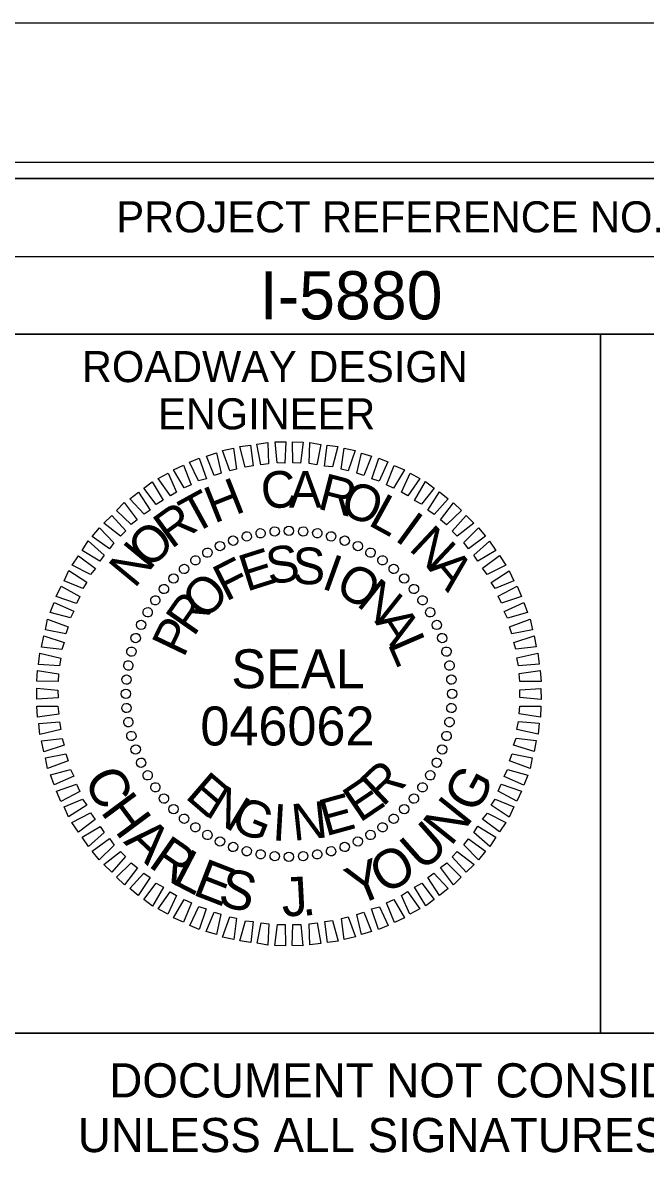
# Model space of a CAD drawing. Extents: x 1648157 to 1650776, y 832691 to 834781.
# Drawn here: x 1650336.4 to 1650436.6, y 833605.5 to 833791 of the extents above; entities that cross this region are included whole.
import ezdxf

# ---------------------------------------------------------------- set-up
doc = ezdxf.new("R2010")
doc.units = 0
for name, color, linetype in [('Default', 7, 'Continuous'), ('Old_Level_2', 7, 'Continuous'), ('Sheet Cutting Line CELL', 7, 'Continuous'), ('Sheet Data Field CELL', 7, 'Continuous'), ('Sheet Plot Border Inside CELL', 7, 'Continuous'), ('Sheet Plot Border Outside CELL', 7, 'Continuous'), ('Sheet Profile CELL', 7, 'Continuous'), ('Sheet Profile Grid Major CELL', 7, 'Continuous'), ('Sheet Sticker Exception Certification CELL', 7, 'Continuous')]:
    doc.layers.add(name, color=color, linetype=linetype)

msp = doc.modelspace()

# ---------------------------------------------------------------- linework, layer by layer
at = {"layer": 'Old_Level_2'}
for p, q in [((1650374.65, 833708.89), (1650374.65, 833708.89)), ((1650376.9, 833709.25), (1650376.9, 833709.25)), ((1650379.2, 833709.34), (1650379.2, 833709.34)), ((1650381.5, 833709.22), (1650381.5, 833709.22)), ((1650383.75, 833708.9), (1650383.75, 833708.9)), ((1650368.1, 833706.9), (1650368.1, 833706.9)), ((1650370.18, 833707.77), (1650370.18, 833707.77)), ((1650372.36, 833708.44), (1650372.36, 833708.44)), ((1650385.96, 833708.46), (1650385.96, 833708.46)), ((1650388.17, 833707.77), (1650388.17, 833707.77)), ((1650390.27, 833706.87), (1650390.27, 833706.87)), ((1650366.08, 833705.82), (1650366.08, 833705.82)), ((1650392.33, 833705.86), (1650392.33, 833705.86)), ((1650362.31, 833703.24), (1650362.31, 833703.24)), ((1650364.11, 833704.58), (1650364.11, 833704.58)), ((1650394.24, 833704.58), (1650394.24, 833704.58)), ((1650396.09, 833703.2), (1650396.09, 833703.2)), ((1650360.61, 833701.64), (1650360.61, 833701.64)), ((1650397.74, 833701.66), (1650397.74, 833701.66)), ((1650359.07, 833699.99), (1650359.07, 833699.99)), ((1650399.34, 833699.96), (1650399.34, 833699.96)), ((1650357.69, 833698.14), (1650357.69, 833698.14)), ((1650400.68, 833698.16), (1650400.68, 833698.16)), ((1650356.42, 833696.23), (1650356.42, 833696.23)), ((1650401.91, 833696.19), (1650401.91, 833696.19)), ((1650355.41, 833694.18), (1650355.41, 833694.18)), ((1650402.99, 833694.17), (1650402.99, 833694.17)), ((1650354.5, 833692.07), (1650354.5, 833692.07)), ((1650403.87, 833692.09), (1650403.87, 833692.09)), ((1650353.81, 833689.86), (1650353.81, 833689.86)), ((1650404.53, 833689.91), (1650404.53, 833689.91)), ((1650353.37, 833687.66), (1650353.37, 833687.66)), ((1650404.99, 833687.62), (1650404.99, 833687.62)), ((1650353.05, 833685.4), (1650353.05, 833685.4)), ((1650405.34, 833685.37), (1650405.34, 833685.37)), ((1650352.93, 833683.1), (1650352.93, 833683.1)), ((1650379.18, 833683.09), (1650379.18, 833683.09)), ((1650405.44, 833683.07), (1650405.44, 833683.07)), ((1650353.02, 833680.8), (1650353.02, 833680.8)), ((1650405.32, 833680.77), (1650405.32, 833680.77)), ((1650353.38, 833678.56), (1650353.38, 833678.56)), ((1650404.99, 833678.52), (1650404.99, 833678.52)), ((1650353.84, 833676.26), (1650353.84, 833676.26)), ((1650404.56, 833676.31), (1650404.56, 833676.31)), ((1650354.5, 833674.08), (1650354.5, 833674.08)), ((1650403.87, 833674.1), (1650403.87, 833674.1)), ((1650355.37, 833672), (1650355.37, 833672)), ((1650402.96, 833672), (1650402.96, 833672)), ((1650356.46, 833669.98), (1650356.46, 833669.98)), ((1650401.95, 833669.94), (1650401.95, 833669.94)), ((1650357.69, 833668.02), (1650357.69, 833668.02)), ((1650400.68, 833668.03), (1650400.68, 833668.03)), ((1650359.03, 833666.21), (1650359.03, 833666.21)), ((1650399.3, 833666.18), (1650399.3, 833666.18)), ((1650360.63, 833664.51), (1650360.63, 833664.51)), ((1650397.76, 833664.53), (1650397.76, 833664.53)), ((1650362.28, 833662.97), (1650362.28, 833662.97)), ((1650396.06, 833662.93), (1650396.06, 833662.93)), ((1650364.13, 833661.59), (1650364.13, 833661.59)), ((1650366.04, 833660.32), (1650366.04, 833660.32)), ((1650392.29, 833660.36), (1650392.29, 833660.36)), ((1650394.25, 833661.59), (1650394.25, 833661.59)), ((1650368.09, 833659.31), (1650368.09, 833659.31)), ((1650390.27, 833659.28), (1650390.27, 833659.28)), ((1650370.2, 833658.4), (1650370.2, 833658.4)), ((1650372.41, 833657.71), (1650372.41, 833657.71)), ((1650374.61, 833657.28), (1650374.61, 833657.28)), ((1650376.87, 833656.95), (1650376.87, 833656.95)), ((1650379.17, 833656.83), (1650379.17, 833656.83)), ((1650381.47, 833656.93), (1650381.47, 833656.93)), ((1650383.71, 833657.28), (1650383.71, 833657.28)), ((1650386.01, 833657.74), (1650386.01, 833657.74)), ((1650388.19, 833658.4), (1650388.19, 833658.4))]:
    msp.add_line(p, q, dxfattribs=at)
for points in [[(1650374.67, 833719.93), (1650374.04, 833723.26), (1650375.81, 833723.5), (1650375.92, 833720.11)], [(1650377.28, 833720.24), (1650376.96, 833723.63), (1650378.69, 833723.61), (1650378.54, 833720.21)], [(1650379.79, 833720.23), (1650379.73, 833723.63), (1650381.46, 833723.6), (1650381.05, 833720.2)], [(1650382.41, 833720.12), (1650382.56, 833723.52), (1650384.29, 833723.23), (1650383.67, 833719.93)], [(1650367.17, 833718.23), (1650365.91, 833721.34), (1650367.53, 833721.84), (1650368.26, 833718.61)], [(1650369.67, 833718.95), (1650368.51, 833722.23), (1650370.28, 833722.62), (1650370.76, 833719.23)], [(1650372.17, 833719.57), (1650371.27, 833722.9), (1650373, 833723.09), (1650373.42, 833719.75)], [(1650384.92, 833719.74), (1650385.34, 833723.1), (1650387.07, 833722.86), (1650386.18, 833719.61)], [(1650387.6, 833719.21), (1650388.06, 833722.62), (1650389.85, 833722.23), (1650388.7, 833718.97)], [(1650390.12, 833718.58), (1650390.85, 833721.83), (1650392.48, 833721.34), (1650391.23, 833718.23)], [(1650362.34, 833716.21), (1650360.62, 833719.11), (1650362.23, 833719.87), (1650363.48, 833716.7)], [(1650364.62, 833717.35), (1650363.21, 833720.36), (1650364.77, 833721.01), (1650365.92, 833717.68)], [(1650392.49, 833717.68), (1650393.64, 833720.99), (1650395.11, 833720.39), (1650393.7, 833717.33)], [(1650394.86, 833716.72), (1650396.11, 833719.83), (1650397.75, 833719.13), (1650396.02, 833716.17)], [(1650360.12, 833714.92), (1650358.13, 833717.71), (1650359.74, 833718.57), (1650361.1, 833715.56)], [(1650397.29, 833715.56), (1650398.65, 833718.57), (1650400.23, 833717.71), (1650398.29, 833714.95)], [(1650357.84, 833713.57), (1650355.86, 833716.2), (1650357.2, 833717.22), (1650358.98, 833714.22)], [(1650399.35, 833714.19), (1650401.13, 833717.25), (1650402.51, 833716.18), (1650400.51, 833713.58)], [(1650355.88, 833711.97), (1650353.59, 833714.44), (1650354.98, 833715.56), (1650356.86, 833712.66)], [(1650401.52, 833712.66), (1650403.41, 833715.57), (1650404.79, 833714.44), (1650402.53, 833711.94)], [(1650353.82, 833710.31), (1650351.48, 833712.57), (1650352.71, 833713.85), (1650354.8, 833711.06)], [(1650403.54, 833711.07), (1650405.63, 833713.83), (1650406.91, 833712.59), (1650404.54, 833710.3)], [(1650352.12, 833708.45), (1650349.42, 833710.55), (1650350.71, 833711.77), (1650352.94, 833709.3)], [(1650405.45, 833709.27), (1650407.66, 833711.77), (1650408.93, 833710.54), (1650406.25, 833708.45)], [(1650350.33, 833706.43), (1650347.57, 833708.42), (1650348.7, 833709.8), (1650351.04, 833707.38)], [(1650407.31, 833707.42), (1650409.68, 833709.82), (1650410.8, 833708.43), (1650408.06, 833706.39)], [(1650348.79, 833704.42), (1650345.94, 833706.14), (1650346.91, 833707.68), (1650349.46, 833705.42)], [(1650408.92, 833705.41), (1650411.44, 833707.65), (1650412.46, 833706.15), (1650409.56, 833704.43)], [(1650347.26, 833702.3), (1650344.31, 833703.81), (1650345.33, 833705.3), (1650348.08, 833703.25)], [(1650410.31, 833703.29), (1650413.05, 833705.33), (1650414.07, 833703.78), (1650411.06, 833702.26)], [(1650346.05, 833700.03), (1650343.04, 833701.28), (1650343.8, 833702.92), (1650346.66, 833701.03)], [(1650411.71, 833701.02), (1650414.61, 833702.9), (1650415.32, 833701.29), (1650412.36, 833700.03)], [(1650345.04, 833697.6), (1650341.78, 833698.75), (1650342.54, 833700.38), (1650345.55, 833698.76)], [(1650412.8, 833698.79), (1650415.86, 833700.41), (1650416.56, 833698.75), (1650413.34, 833697.65)], [(1650344.04, 833695.29), (1650340.78, 833696.17), (1650341.43, 833697.8), (1650344.59, 833696.39)], [(1650413.78, 833696.35), (1650416.95, 833697.76), (1650417.55, 833696.15), (1650414.32, 833695.26)], [(1650343.3, 833692.76), (1650340.04, 833693.39), (1650340.38, 833695.12), (1650343.7, 833693.87)], [(1650414.66, 833693.85), (1650417.99, 833695.11), (1650418.33, 833693.39), (1650415.05, 833692.76)], [(1650342.66, 833690.24), (1650339.41, 833690.6), (1650339.75, 833692.39), (1650343.06, 833691.35)], [(1650415.33, 833691.35), (1650418.61, 833692.4), (1650418.95, 833690.63), (1650415.67, 833690.26)], [(1650342.29, 833687.57), (1650338.94, 833687.82), (1650339.12, 833689.6), (1650342.53, 833688.83)], [(1650415.85, 833688.85), (1650419.23, 833689.64), (1650419.42, 833687.87), (1650416.08, 833687.6)], [(1650342.07, 833685.05), (1650338.67, 833685.1), (1650338.75, 833686.83), (1650342.15, 833686.31)], [(1650416.21, 833686.35), (1650419.6, 833686.82), (1650419.73, 833685.05), (1650416.33, 833685.09)], [(1650342.07, 833682.44), (1650338.67, 833682.22), (1650338.64, 833684), (1650342.04, 833683.69)], [(1650416.3, 833683.73), (1650419.7, 833683.95), (1650419.73, 833682.17), (1650416.33, 833682.48)], [(1650342.16, 833679.83), (1650338.77, 833679.35), (1650338.64, 833681.12), (1650342.04, 833681.08)], [(1650416.3, 833681.12), (1650419.7, 833681.07), (1650419.62, 833679.35), (1650416.21, 833679.86)], [(1650342.52, 833677.32), (1650339.14, 833676.53), (1650338.95, 833678.3), (1650342.29, 833678.57)], [(1650416.08, 833678.61), (1650419.43, 833678.35), (1650419.25, 833676.57), (1650415.84, 833677.35)], [(1650343.04, 833674.82), (1650339.76, 833673.77), (1650339.41, 833675.54), (1650342.7, 833675.91)], [(1650415.71, 833675.93), (1650418.96, 833675.57), (1650418.62, 833673.79), (1650415.31, 833674.83)], [(1650343.71, 833672.32), (1650340.38, 833671.06), (1650340.04, 833672.78), (1650343.32, 833673.41)], [(1650415.07, 833673.41), (1650418.32, 833672.79), (1650417.99, 833671.06), (1650414.67, 833672.31)], [(1650344.59, 833669.83), (1650341.42, 833668.41), (1650340.82, 833670.02), (1650344.04, 833670.92)], [(1650414.33, 833670.89), (1650417.59, 833670), (1650416.94, 833668.37), (1650413.78, 833669.78)], [(1650345.57, 833667.39), (1650342.51, 833665.76), (1650341.8, 833667.42), (1650345.03, 833668.53)], [(1650413.33, 833668.57), (1650416.59, 833667.42), (1650415.83, 833665.79), (1650412.82, 833667.41)], [(1650346.66, 833665.16), (1650343.76, 833663.28), (1650343.05, 833664.88), (1650346.01, 833666.14)], [(1650412.32, 833666.15), (1650415.33, 833664.89), (1650414.57, 833663.26), (1650411.71, 833665.14)], [(1650348.05, 833662.88), (1650345.32, 833660.84), (1650344.3, 833662.4), (1650347.3, 833663.91)], [(1650411.11, 833663.88), (1650414.06, 833662.36), (1650413.04, 833660.88), (1650410.29, 833662.92)], [(1650349.45, 833660.76), (1650346.93, 833658.52), (1650345.91, 833660.02), (1650348.81, 833661.74)], [(1650409.57, 833661.76), (1650412.43, 833660.03), (1650411.46, 833658.5), (1650408.91, 833660.75)], [(1650351.06, 833658.75), (1650348.69, 833656.35), (1650347.57, 833657.75), (1650350.31, 833659.78)], [(1650408.04, 833659.74), (1650410.8, 833657.75), (1650409.67, 833656.37), (1650407.33, 833658.79)], [(1650352.92, 833656.9), (1650350.71, 833654.4), (1650349.44, 833655.63), (1650352.12, 833657.72)], [(1650406.25, 833657.72), (1650408.95, 833655.63), (1650407.66, 833654.4), (1650405.42, 833656.87)], [(1650354.83, 833655.1), (1650352.74, 833652.35), (1650351.46, 833653.58), (1650353.83, 833655.87)], [(1650404.55, 833655.86), (1650406.89, 833653.6), (1650405.66, 833652.33), (1650403.57, 833655.12)], [(1650356.85, 833653.52), (1650354.96, 833650.61), (1650353.58, 833651.73), (1650355.84, 833654.23)], [(1650402.49, 833654.21), (1650404.78, 833651.74), (1650403.39, 833650.61), (1650401.51, 833653.51)], [(1650359.02, 833651.98), (1650357.24, 833648.92), (1650355.86, 833649.99), (1650357.86, 833652.59)], [(1650361.08, 833650.61), (1650359.72, 833647.6), (1650358.14, 833648.46), (1650360.08, 833651.22)], [(1650398.25, 833651.26), (1650400.24, 833648.47), (1650398.63, 833647.6), (1650397.27, 833650.61)], [(1650400.53, 833652.6), (1650402.51, 833649.97), (1650401.17, 833648.95), (1650399.39, 833651.96)], [(1650363.51, 833649.45), (1650362.25, 833646.34), (1650360.62, 833647.04), (1650362.35, 833650)], [(1650396.03, 833649.96), (1650397.75, 833647.06), (1650396.14, 833646.3), (1650394.88, 833649.47)], [(1650365.88, 833648.5), (1650364.73, 833645.18), (1650363.26, 833645.78), (1650364.67, 833648.84)], [(1650368.25, 833647.6), (1650367.52, 833644.34), (1650365.89, 833644.83), (1650367.14, 833647.94)], [(1650391.2, 833647.94), (1650392.46, 833644.83), (1650390.84, 833644.33), (1650390.11, 833647.56)], [(1650393.75, 833648.82), (1650395.16, 833645.82), (1650393.6, 833645.16), (1650392.44, 833648.49)], [(1650370.77, 833646.96), (1650370.3, 833643.55), (1650368.52, 833643.94), (1650369.67, 833647.2)], [(1650373.44, 833646.43), (1650373.03, 833643.08), (1650371.3, 833643.31), (1650372.19, 833646.57)], [(1650375.96, 833646.06), (1650375.81, 833642.65), (1650374.08, 833642.94), (1650374.7, 833646.24)], [(1650378.58, 833645.95), (1650378.64, 833642.55), (1650376.91, 833642.57), (1650377.32, 833645.98)], [(1650381.09, 833645.94), (1650381.41, 833642.54), (1650379.68, 833642.57), (1650379.83, 833645.97)], [(1650383.7, 833646.24), (1650384.33, 833642.91), (1650382.56, 833642.67), (1650382.45, 833646.07)], [(1650386.2, 833646.6), (1650387.1, 833643.27), (1650385.37, 833643.08), (1650384.95, 833646.42)], [(1650388.7, 833647.22), (1650389.86, 833643.95), (1650388.09, 833643.55), (1650387.61, 833646.94)]]:
    msp.add_lwpolyline(points, close=True, dxfattribs=at)
for centre, major_axis in [((1650370.21, 833707.73), (-0.258, 0.708)), ((1650372.4, 833708.42), (-0.195, 0.727)), ((1650374.63, 833708.92), (-0.131, 0.742)), ((1650376.9, 833709.21), (-0.066, 0.75)), ((1650379.18, 833709.31), (0, 0.753)), ((1650381.47, 833709.21), (0.066, 0.75)), ((1650383.74, 833708.92), (0.131, 0.742)), ((1650385.97, 833708.42), (0.195, 0.727)), ((1650388.15, 833707.73), (0.258, 0.708)), ((1650368.1, 833706.86), (-0.318, 0.682)), ((1650390.27, 833706.86), (0.318, 0.682)), ((1650364.14, 833704.57), (-0.432, 0.617)), ((1650366.07, 833705.8), (-0.376, 0.652)), ((1650392.3, 833705.8), (0.376, 0.652)), ((1650394.23, 833704.57), (0.432, 0.617)), ((1650362.33, 833703.18), (-0.484, 0.577)), ((1650396.04, 833703.18), (0.484, 0.577)), ((1650360.64, 833701.63), (-0.532, 0.532)), ((1650397.73, 833701.63), (0.532, 0.532)), ((1650359.09, 833699.95), (-0.577, 0.484)), ((1650399.28, 833699.95), (0.577, 0.484)), ((1650357.7, 833698.13), (-0.617, 0.432)), ((1650400.67, 833698.13), (0.617, 0.432)), ((1650356.47, 833696.2), (-0.652, 0.376)), ((1650401.9, 833696.2), (0.652, 0.376)), ((1650355.41, 833694.17), (-0.682, 0.318)), ((1650402.95, 833694.17), (0.682, 0.318)), ((1650354.54, 833692.06), (-0.708, 0.258)), ((1650403.83, 833692.06), (0.708, 0.258)), ((1650353.85, 833689.87), (-0.727, 0.195)), ((1650404.52, 833689.87), (0.727, 0.195)), ((1650353.36, 833687.64), (-0.742, 0.131)), ((1650405.01, 833687.64), (0.742, 0.131)), ((1650353.06, 833685.37), (-0.75, 0.066)), ((1650405.31, 833685.37), (0.75, 0.066)), ((1650352.96, 833683.09), (-0.753, 0)), ((1650405.41, 833683.09), (0.753, 0)), ((1650353.06, 833680.8), (-0.75, -0.066)), ((1650405.31, 833680.8), (0.75, -0.066)), ((1650353.36, 833678.53), (-0.742, -0.131)), ((1650405.01, 833678.53), (0.742, -0.131)), ((1650353.85, 833676.3), (-0.727, -0.195)), ((1650404.52, 833676.3), (0.727, -0.195)), ((1650354.54, 833674.12), (-0.708, -0.258)), ((1650403.83, 833674.12), (0.708, -0.258)), ((1650355.41, 833672), (-0.682, -0.318)), ((1650402.95, 833672), (0.682, -0.318)), ((1650356.47, 833669.97), (-0.652, -0.376)), ((1650401.9, 833669.97), (0.652, -0.376)), ((1650357.7, 833668.04), (-0.617, -0.432)), ((1650400.67, 833668.04), (0.617, -0.432)), ((1650359.09, 833666.23), (-0.577, -0.484)), ((1650399.28, 833666.23), (0.577, -0.484)), ((1650360.64, 833664.54), (-0.532, -0.532)), ((1650397.73, 833664.54), (0.532, -0.532)), ((1650362.33, 833662.99), (-0.484, -0.577)), ((1650364.14, 833661.6), (-0.432, -0.617)), ((1650394.23, 833661.6), (0.432, -0.617)), ((1650396.04, 833662.99), (0.484, -0.577)), ((1650366.07, 833660.37), (-0.376, -0.652)), ((1650392.3, 833660.37), (0.376, -0.652)), ((1650368.1, 833659.32), (-0.318, -0.682)), ((1650370.21, 833658.44), (-0.258, -0.708)), ((1650372.4, 833657.75), (-0.195, -0.727)), ((1650385.97, 833657.75), (0.195, -0.727)), ((1650388.15, 833658.44), (0.258, -0.708)), ((1650390.27, 833659.32), (0.318, -0.682)), ((1650374.63, 833657.26), (-0.131, -0.742)), ((1650376.9, 833656.96), (-0.066, -0.75)), ((1650379.18, 833656.86), (0, -0.753)), ((1650381.47, 833656.96), (0.066, -0.75)), ((1650383.74, 833657.26), (0.131, -0.742))]:
    msp.add_ellipse(centre, major_axis=major_axis, ratio=0.999708, dxfattribs=at)
at = {"layer": 'Sheet Cutting Line CELL'}
msp.add_line((1650546.28, 833791.02), (1648862.28, 833791.02), dxfattribs=at)
at = {"layer": 'Sheet Plot Border Inside CELL'}
msp.add_lwpolyline([(1648875.28, 832713.47), (1650541.78, 832713.47), (1650541.78, 833768.57), (1648875.28, 833768.57)], close=True, dxfattribs=at)
at = {"layer": 'Sheet Plot Border Outside CELL'}
msp.add_lwpolyline([(1648862.28, 832691.02), (1650546.28, 832691.02), (1650546.28, 833791.02), (1648862.28, 833791.02)], close=True, dxfattribs=at)
at = {"layer": 'Sheet Profile CELL'}
for p, q in [((1650329.23, 833753.47), (1650529.28, 833753.47)), ((1650429.28, 833740.97), (1650429.28, 833628.52))]:
    msp.add_line(p, q, dxfattribs=at)
for points in [[(1650529.28, 833766.02), (1649029.28, 833766.02), (1649029.28, 832716.02), (1650529.28, 832716.02)], [(1650329.23, 833766.02), (1650529.28, 833766.02), (1650529.28, 833740.97), (1650329.23, 833740.97)], [(1650329.23, 833740.97), (1650429.28, 833740.97), (1650429.28, 833628.47), (1650329.23, 833628.47)], [(1650429.28, 833740.97), (1650529.28, 833740.97), (1650529.28, 833628.47), (1650429.28, 833628.47)]]:
    msp.add_lwpolyline(points, close=True, dxfattribs=at)
at = {"layer": 'Sheet Profile Grid Major CELL'}
msp.add_lwpolyline([(1650279.23, 833738.96), (1650279.23, 833266.02), (1650329.23, 833266.02), (1650329.23, 833766.02), (1650355.53, 833766.02)], dxfattribs=at)
at = {"layer": 'Sheet Sticker Exception Certification CELL'}
msp.add_line((1650329.23, 833628.47), (1650529.27, 833628.47), dxfattribs=at)
msp.add_line((1650329.23, 833628.47), (1650529.27, 833628.47), dxfattribs=at)

# ---------------------------------------------------------------- texts
at = {"layer": 'Default'}
for s, rotation, p in [('C', 297.1999, (1650346.07, 833669.36)), ('G', 61.7998, (1650409.3, 833663.59)), ('H', 306.6436, (1650348.76, 833664.11)), ('N', 51.2288, (1650405.21, 833658.4)), ('U', 41.4347, (1650400.63, 833654.33)), ('A', 316.4834, (1650352.45, 833659.18)), ('R', 325.1961, (1650356.38, 833655.41)), ('L', 332.5683, (1650360.12, 833652.71)), ('Y', 22.2426, (1650390, 833648.88)), ('O', 30.0413, (1650394.53, 833650.66)), ('E', 338.7525, (1650363.5, 833650.83)), ('S', 345.7591, (1650367.55, 833649.16)), ('J', 3.0321, (1650378.14, 833647.23)), ('.', 8.214, (1650381.39, 833647.28))]:
    msp.add_text(s, height=6.27, rotation=rotation, dxfattribs=at).set_placement(p)
at = {"layer": 'Old_Level_2'}
for s, rotation, p in [('C', 7.2199, (1650375.06, 833712.67)), ('A', 0.0203, (1650379.18, 833713.05)), ('R', 345.6211, (1650383.58, 833712.92)), ('T', 28.8198, (1650363.78, 833708.65)), ('H', 21.6195, (1650367.15, 833710.44)), ('O', 338.4212, (1650387.1, 833712.2)), ('L', 331.2209, (1650391.73, 833710.34)), ('R', 36.0205, (1650360.27, 833706.29)), ('I', 324.0201, (1650396.01, 833707.91)), ('O', 43.2217, (1650356.72, 833702.99)), ('N', 316.8189, (1650398.29, 833706.33)), ('N', 50.4235, (1650354.36, 833699.91)), ('S', 8.2556, (1650375.95, 833700.65)), ('S', 358.9004, (1650379.71, 833700.77)), ('F', 26.967, (1650369.04, 833697.87)), ('E', 17.6111, (1650372.36, 833699.49)), ('I', 340.1896, (1650384.22, 833700.12)), ('A', 309.6172, (1650401.42, 833703.29)), ('O', 330.8335, (1650386.33, 833699.42)), ('O', 45.6812, (1650365.65, 833694.72)), ('N', 321.4766, (1650389.86, 833697.39)), ('R', 55.0397, (1650363.86, 833692.13)), ('A', 302.7603, (1650392.89, 833694.73)), ('P', 64.3989, (1650362.25, 833688.75)), ('L', 293.4009, (1650394.99, 833691.15)), ('R', 43.4814, (1650394.25, 833664.78)), ('E', 319.2769, (1650362.32, 833666.42)), ('E', 34.1241, (1650390.58, 833662.26)), ('N', 328.634, (1650365.51, 833663.65)), ('G', 337.9902, (1650369.52, 833661.37)), ('E', 15.4118, (1650385.08, 833660.13)), ('I', 356.7012, (1650376.41, 833659.5)), ('N', 6.0564, (1650379.91, 833659.41))]:
    msp.add_text(s, height=5.9, rotation=rotation, dxfattribs=at).set_placement(p)
for s, height, p in [('SEAL', 6.273, (1650369.91, 833683.97)), ('046062', 6.275, (1650364.94, 833674.77))]:
    msp.add_text(s, height=height, dxfattribs=at).set_placement(p)
at = {"layer": 'Sheet Data Field CELL'}
msp.add_text('I-5880', height=7.75, dxfattribs=at).set_placement((1650374.49, 833743.34))
at = {"layer": 'Sheet Profile CELL'}
for s, height, p in [('PROJECT REFERENCE NO.', 5.0001, (1650351.44, 833757.34)), ('ROADWAY DESIGN', 5.0001, (1650345.89, 833733.24)), ('ENGINEER', 5, (1650358.14, 833725.64))]:
    msp.add_text(s, height=height, dxfattribs=at).set_placement(p)
at = {"layer": 'Sheet Sticker Exception Certification CELL'}
for s, p in [('DOCUMENT NOT CONSIDERED FINAL', (1650350.3, 833618.13)), ('DOCUMENT NOT CONSIDERED FINAL', (1650350.3, 833618.13)), ('UNLESS ALL SIGNATURES COMPLETED', (1650345.23, 833609.33)), ('UNLESS ALL SIGNATURES COMPLETED', (1650345.23, 833609.33))]:
    msp.add_text(s, height=5.5, dxfattribs=at).set_placement(p)

doc.saveas('drawing.dxf')
